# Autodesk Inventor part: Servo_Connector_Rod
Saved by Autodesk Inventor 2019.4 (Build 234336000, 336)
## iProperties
Created: 2020-02
Part Number: Servo_Connector_Rod
Material: Generic
Document SubType Name: Modeling
Designer: Administrator
Density: 1 g/cm^3
Appearance: Default
Title: Servo_Connector_Rod v1
Author: Administrator
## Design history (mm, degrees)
feature "Body1"
body "Solid1"
